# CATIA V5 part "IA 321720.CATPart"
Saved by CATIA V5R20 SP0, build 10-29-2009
Part number: IA 321720
Revision: ANY
Definition: UNKNOWN
Nomenclature: IA 321720
Source: Unknown
Bounding box of the stored display mesh (mm): x -1.6 to 1.6, y -8.75 to 8.2, z -1.6 to 1.6
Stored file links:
  C:\Users\Utente\Desktop\IO LAVORO\3D X SITO CF\CUMSA\3D files FA\FA 063212-20\IA 321720.CATPart

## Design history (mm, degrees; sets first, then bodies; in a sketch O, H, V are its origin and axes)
Body1 "Cortar-Extruir4" (main body)
  Solid1: solid without history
